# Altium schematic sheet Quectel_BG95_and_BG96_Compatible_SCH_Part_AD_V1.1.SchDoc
size 840 x 594 mm
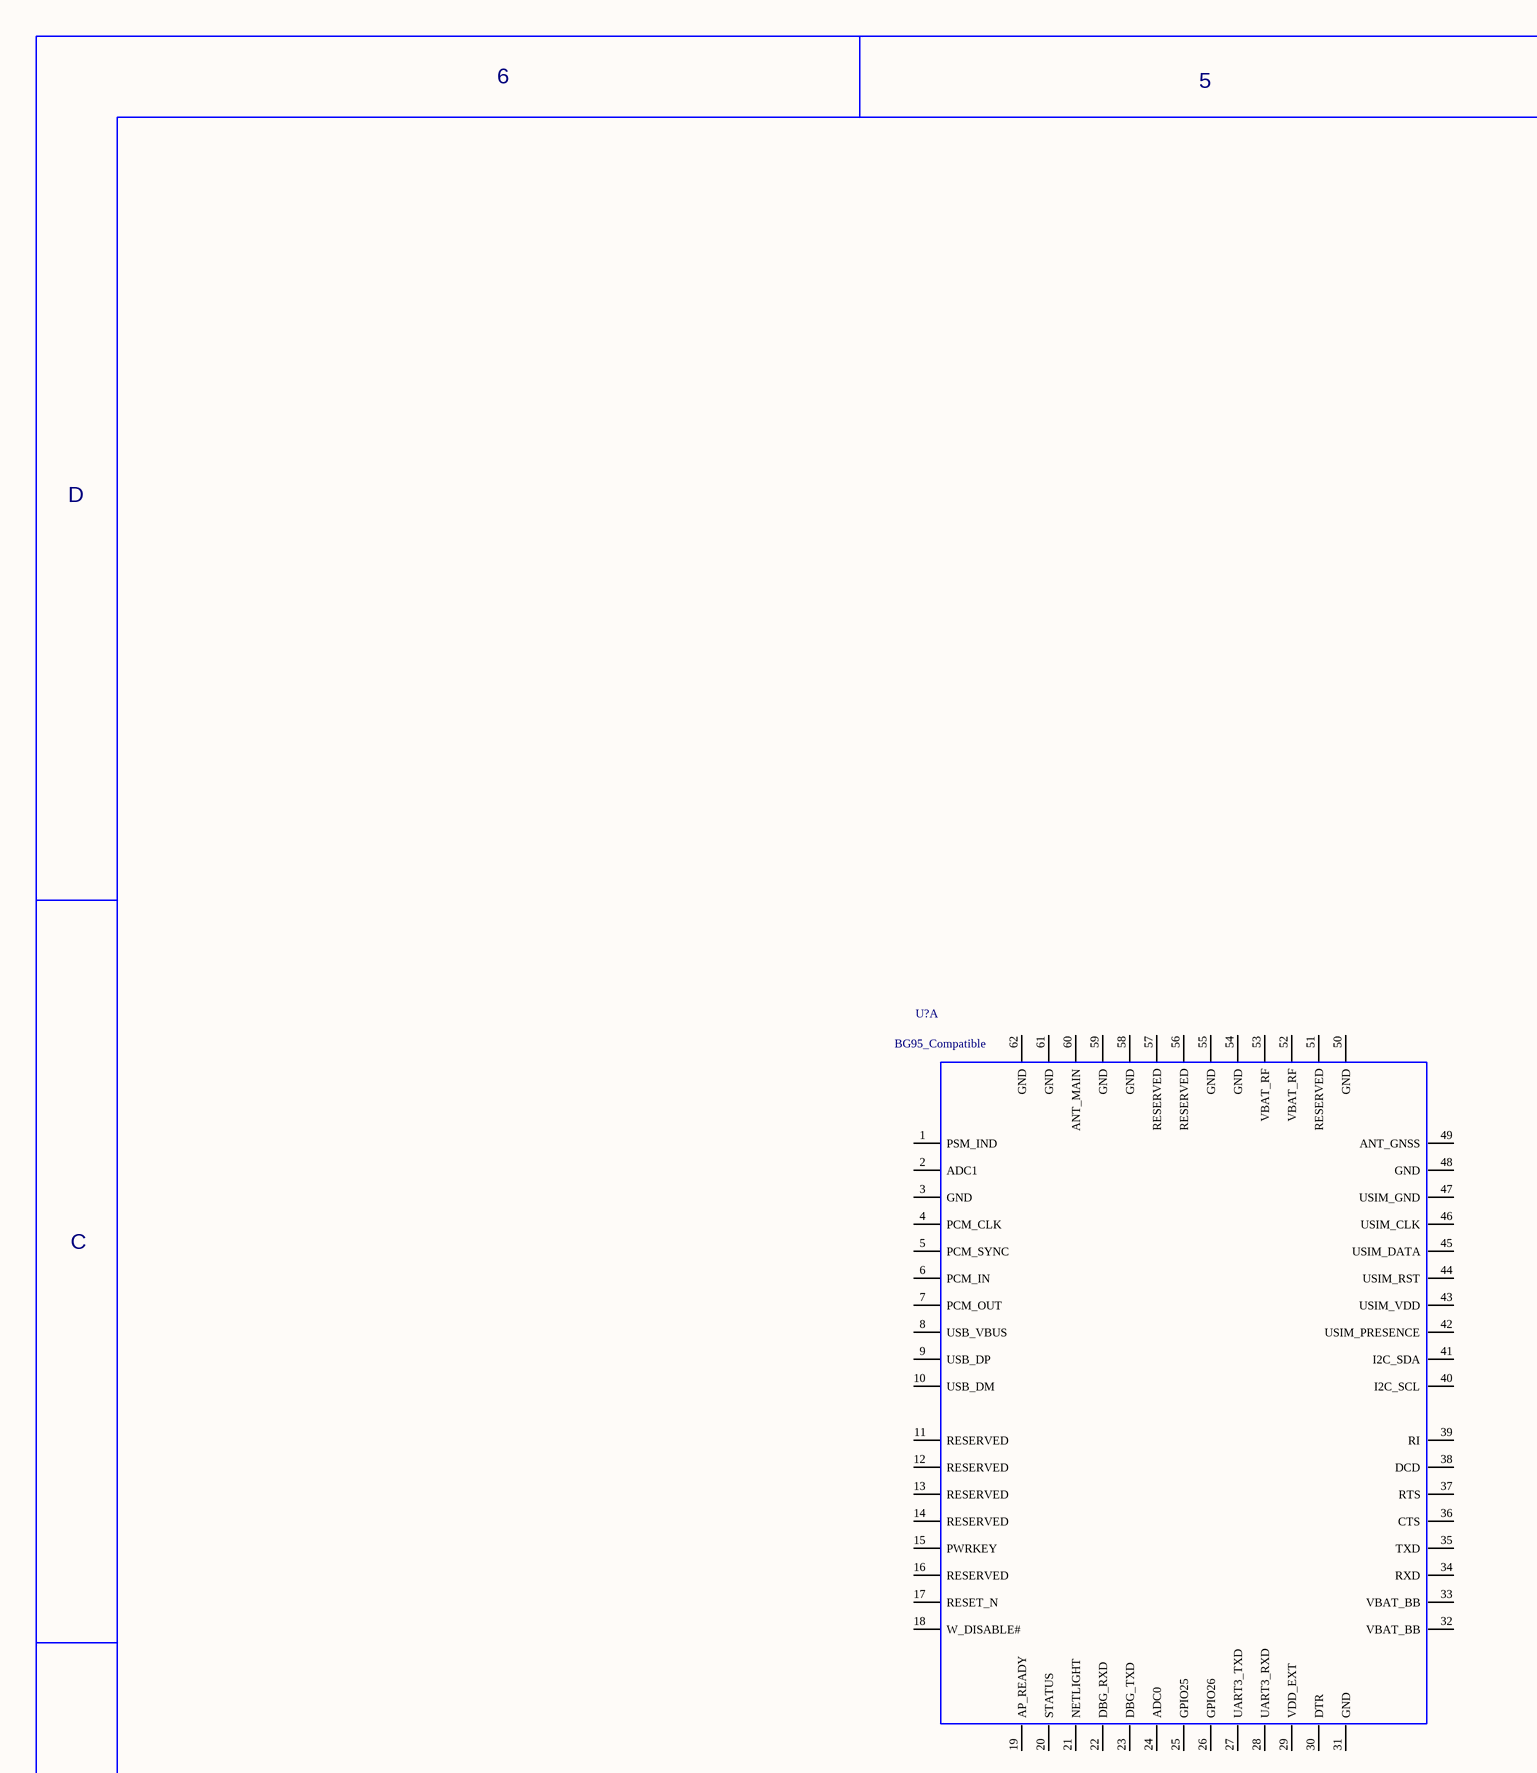
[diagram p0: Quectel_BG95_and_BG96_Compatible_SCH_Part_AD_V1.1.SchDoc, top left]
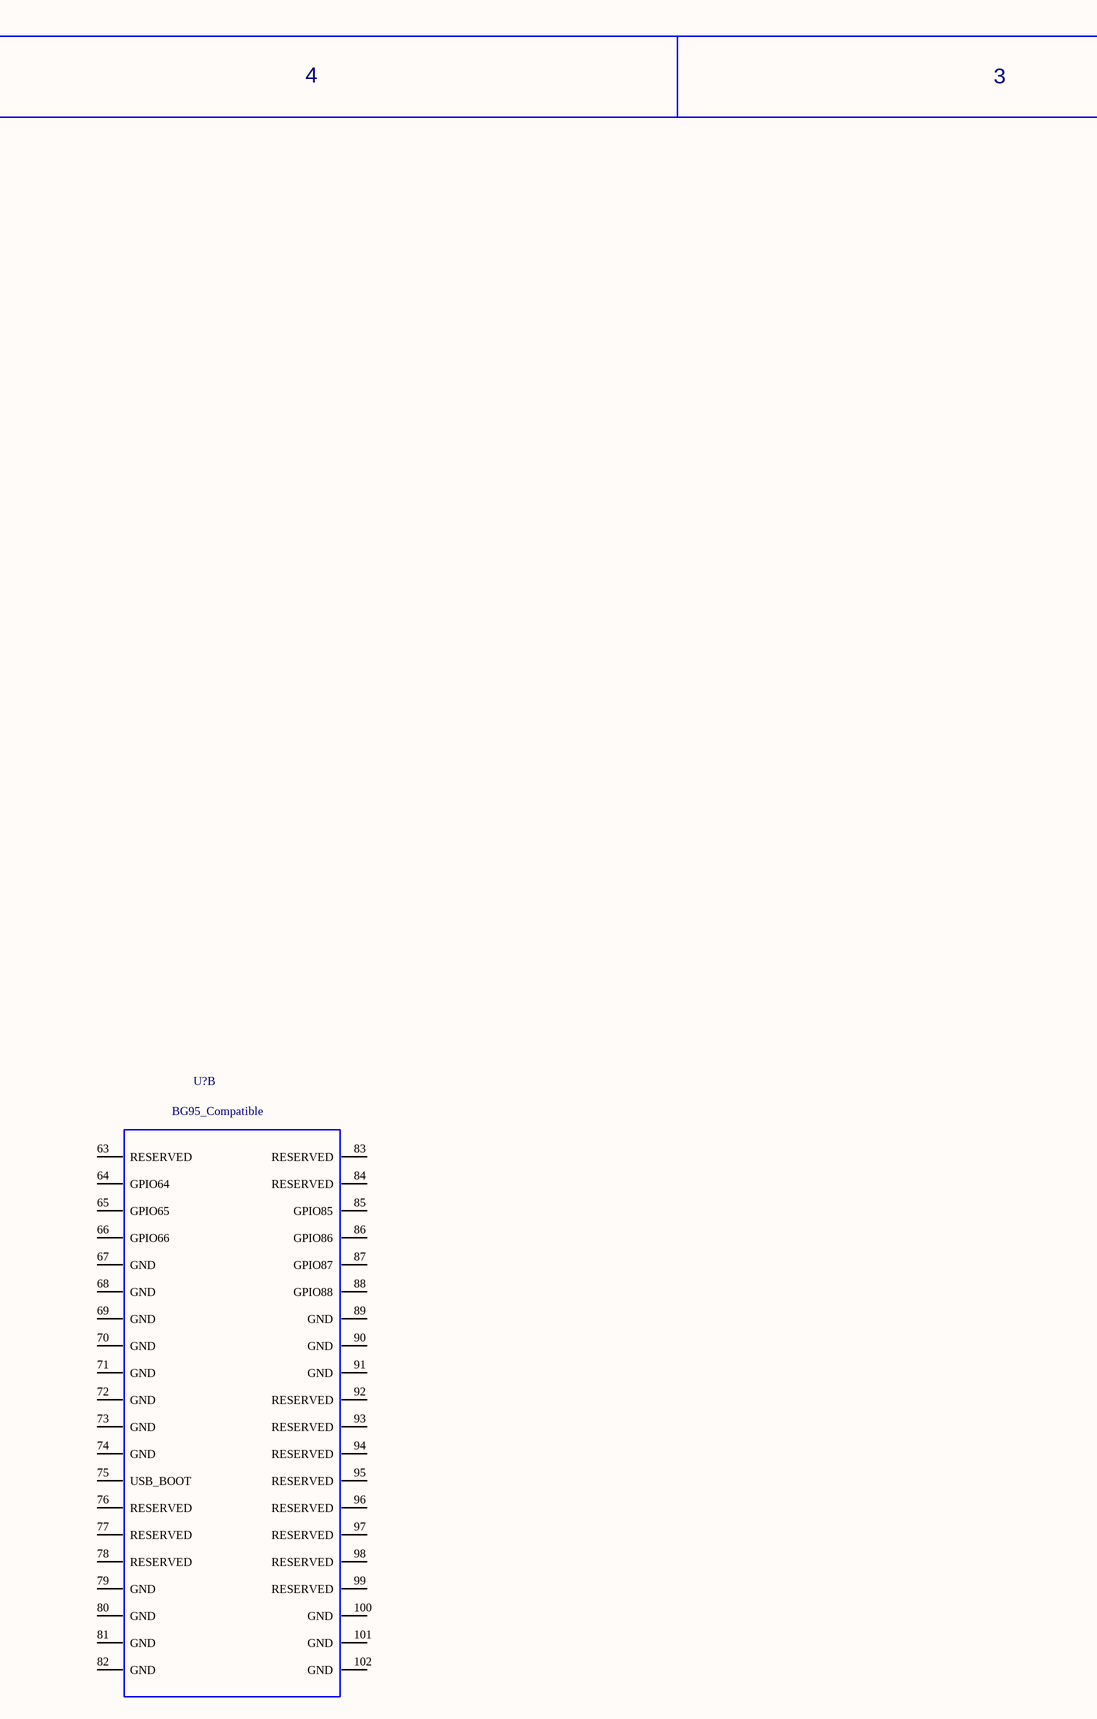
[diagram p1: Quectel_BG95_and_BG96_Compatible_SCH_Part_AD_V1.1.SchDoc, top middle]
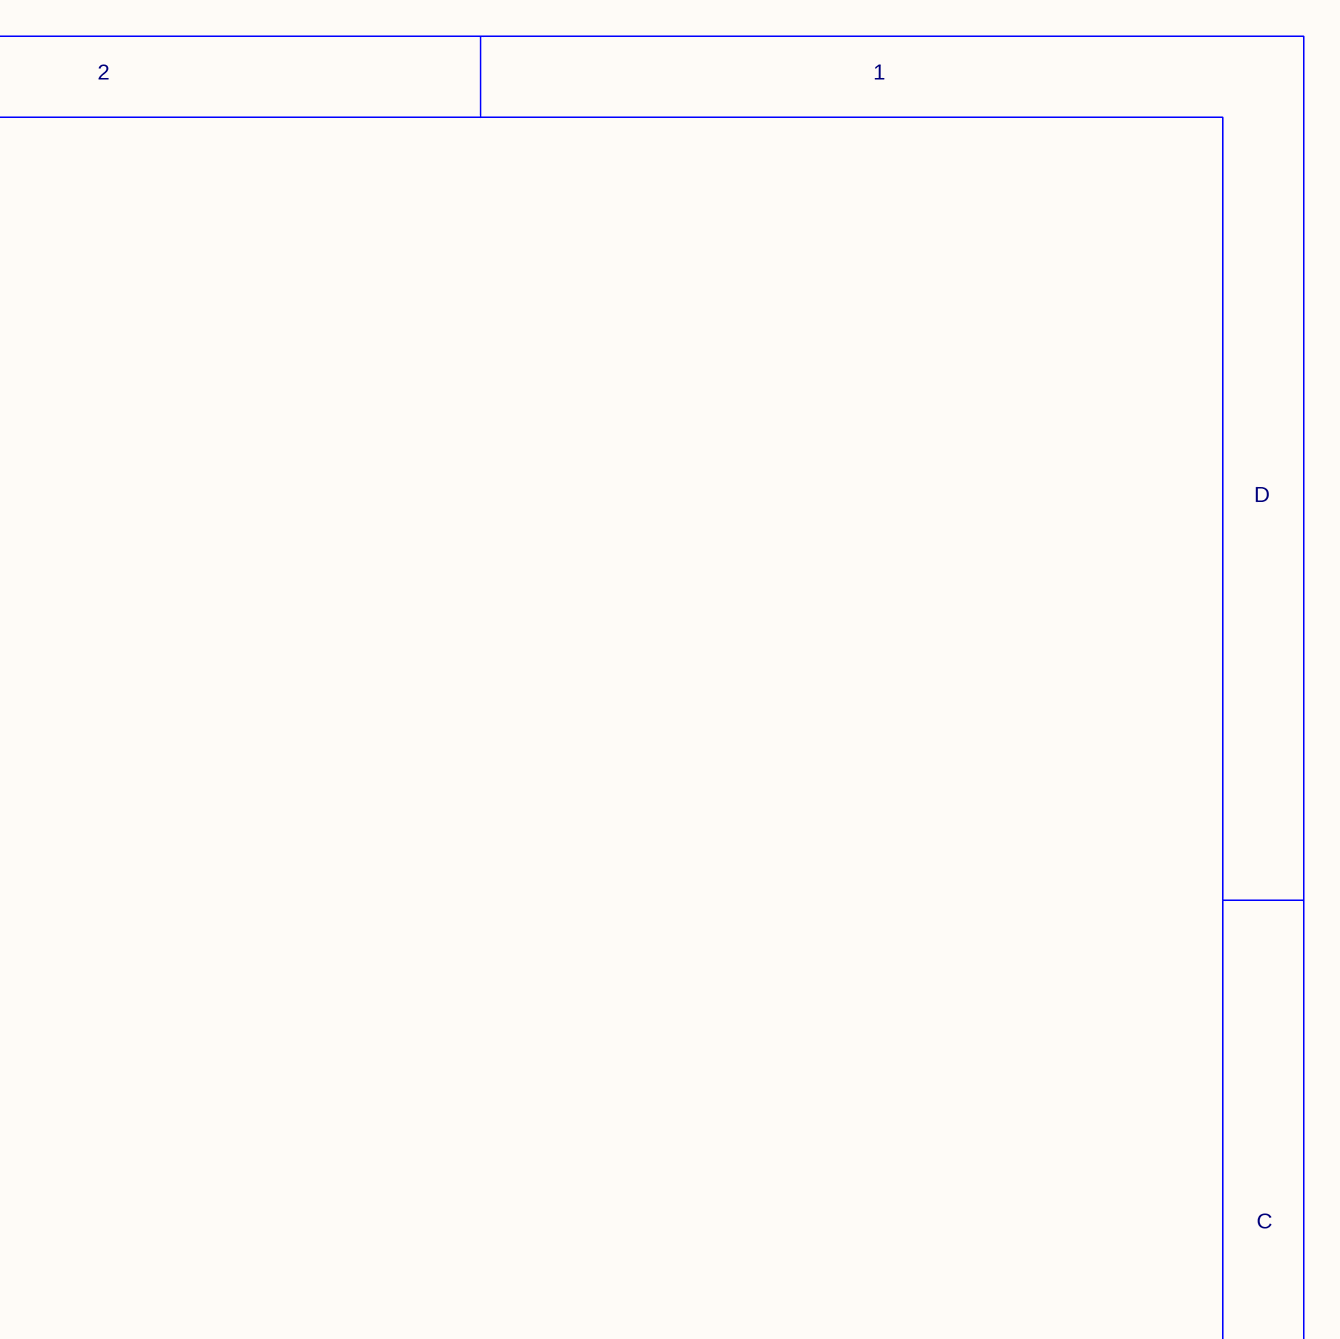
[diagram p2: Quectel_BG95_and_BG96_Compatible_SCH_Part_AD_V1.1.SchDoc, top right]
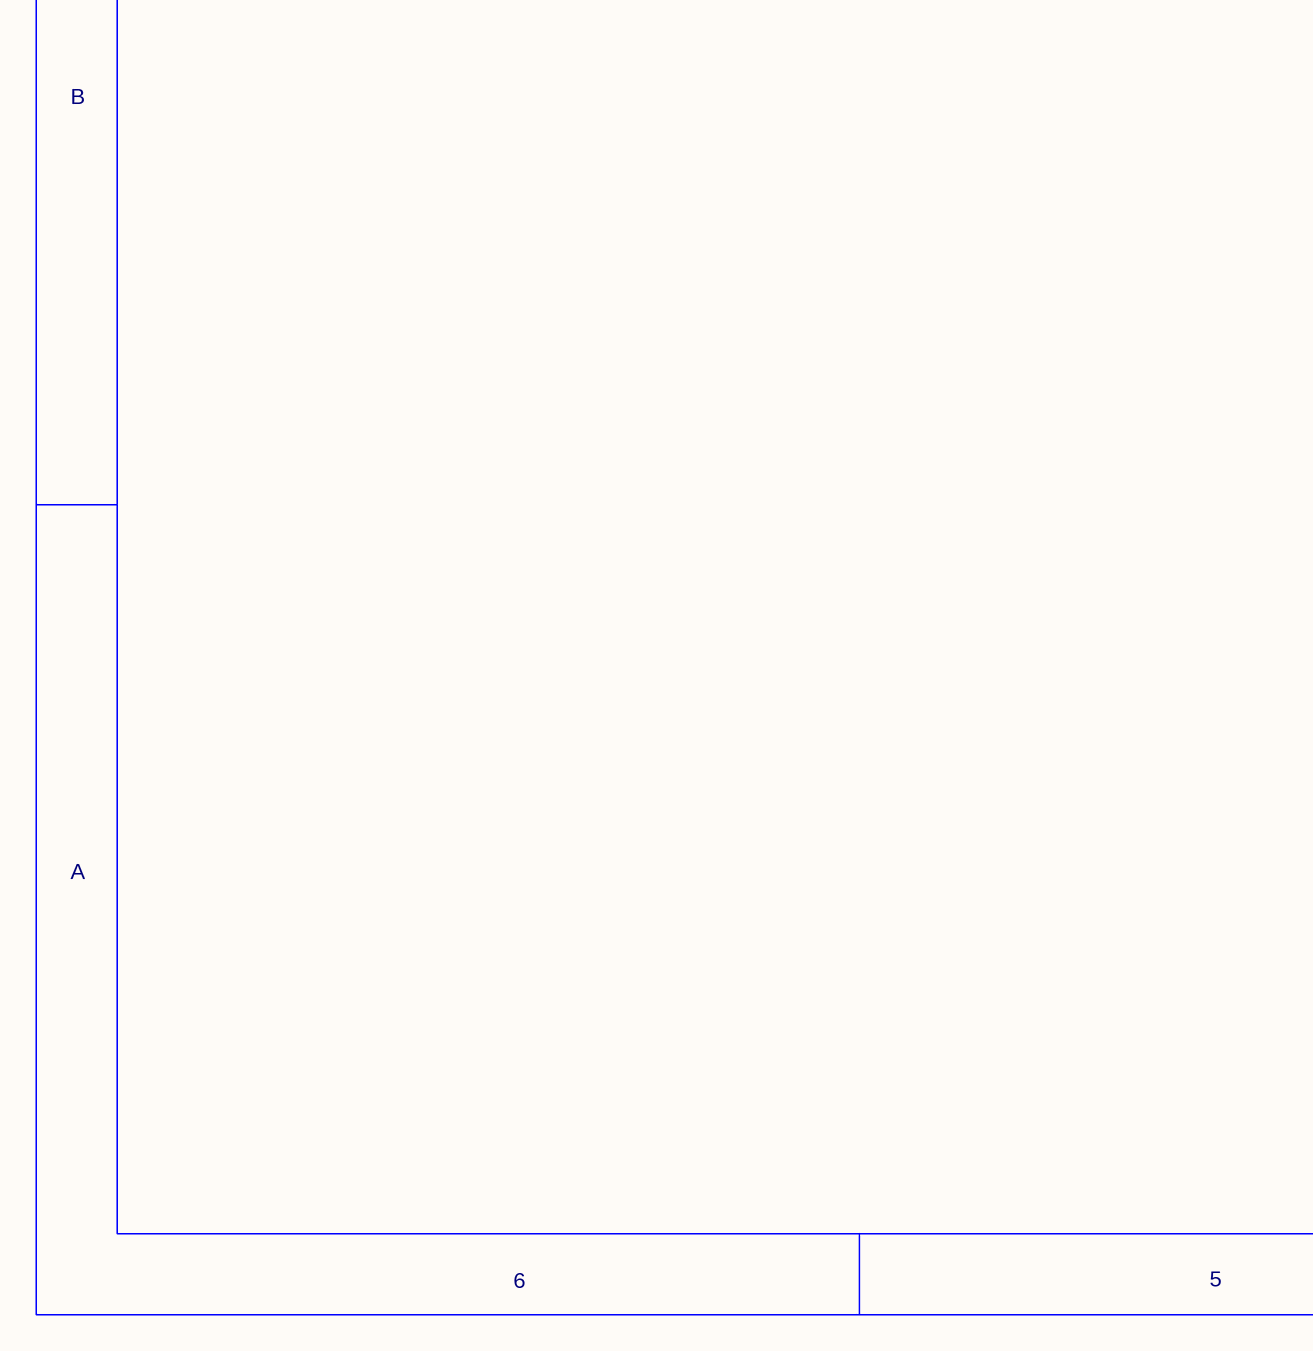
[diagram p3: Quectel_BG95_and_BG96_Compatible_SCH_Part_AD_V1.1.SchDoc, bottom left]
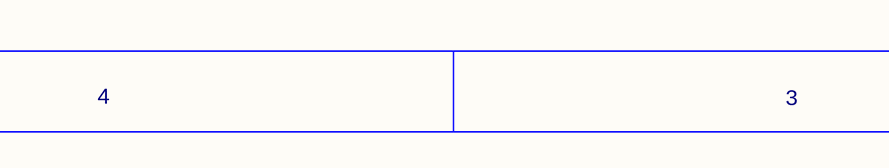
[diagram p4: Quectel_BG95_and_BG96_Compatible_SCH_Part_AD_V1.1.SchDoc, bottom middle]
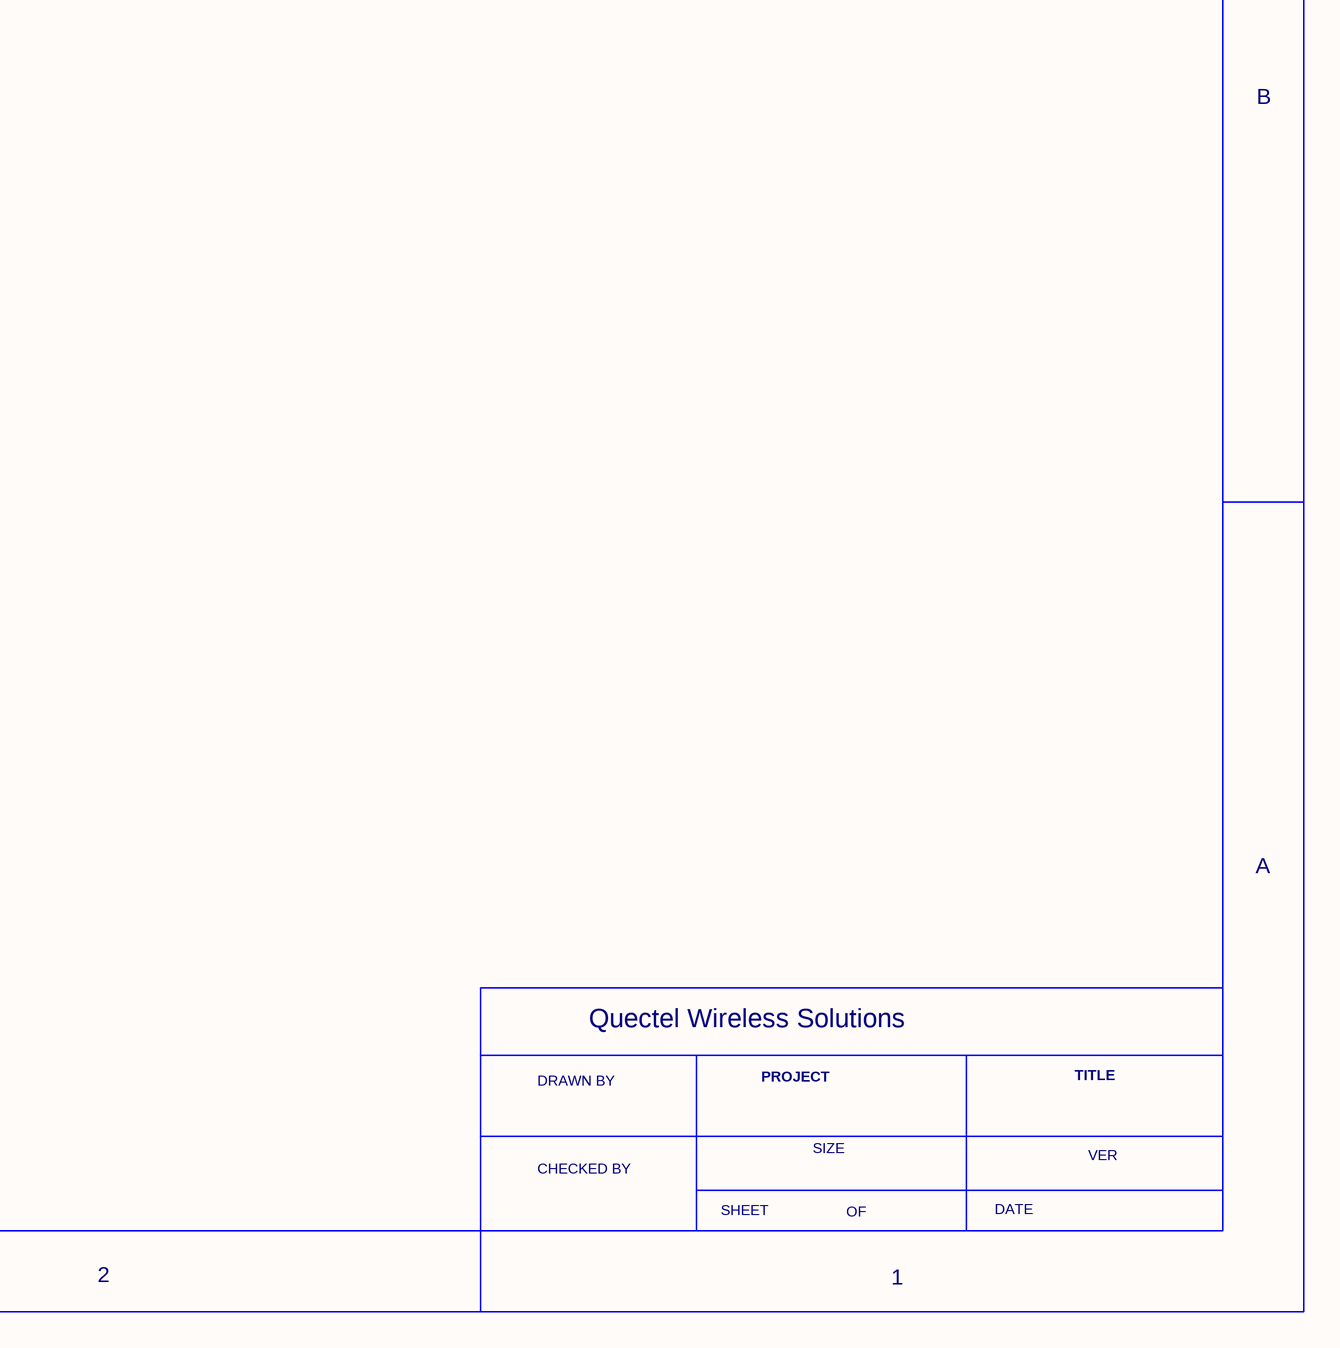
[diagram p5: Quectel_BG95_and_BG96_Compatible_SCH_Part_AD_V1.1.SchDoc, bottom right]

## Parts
(Parts that share a designator on the sheet are numbered #1, #2 ... from top to bottom, then left to right.)
U?#1  BG95_Compatible  [BG95_Compatible]  (part A of 2)
U?#2  BG95_Compatible  [BG95_Compatible]  (part B of 2)

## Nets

Not connected (* = marked no-connect by the designer): U?#1 1(PSM_IND) 2(ADC1) 3(GND) 4(PCM_CLK) 5(PCM_SYNC) 6(PCM_IN) 7(PCM_OUT) 8(USB_VBUS) 9(USB_DP) 10(USB_DM) 11(RESERVED) 12(RESERVED) 13(RESERVED) 14(RESERVED) 15(PWRKEY) 16(RESERVED) 17(RESET_N) 18(W_DISABLE#) 19(AP_READY) 20(STATUS) 21(NETLIGHT) 22(DBG_RXD) 23(DBG_TXD) 24(ADC0) 25(GPIO25) 26(GPIO26) 27(UART3_TXD) 28(UART3_RXD) 29(VDD_EXT) 30(DTR) 31(GND) 32(VBAT_BB) 33(VBAT_BB) 34(RXD) 35(TXD) 36(CTS) 37(RTS) 38(DCD) 39(RI) 40(I2C_SCL) 41(I2C_SDA) 42(USIM_PRESENCE) 43(USIM_VDD) 44(USIM_RST) 45(USIM_DATA) 46(USIM_CLK) 47(USIM_GND) 48(GND) 49(ANT_GNSS) 50(GND) 51(RESERVED) 52(VBAT_RF) 53(VBAT_RF) 54(GND) 55(GND) 56(RESERVED) 57(RESERVED) 58(GND) 59(GND) 60(ANT_MAIN) 61(GND) 62(GND); U?#2 63(RESERVED) 64(GPIO64) 65(GPIO65) 66(GPIO66) 67(GND) 68(GND) 69(GND) 70(GND) 71(GND) 72(GND) 73(GND) 74(GND) 75(USB_BOOT) 76(RESERVED) 77(RESERVED) 78(RESERVED) 79(GND) 80(GND) 81(GND) 82(GND) 83(RESERVED) 84(RESERVED) 85(GPIO85) 86(GPIO86) 87(GPIO87) 88(GPIO88) 89(GND) 90(GND) 91(GND) 92(RESERVED) 93(RESERVED) 94(RESERVED) 95(RESERVED) 96(RESERVED) 97(RESERVED) 98(RESERVED) 99(RESERVED) 100(GND) 101(GND) 102(GND)

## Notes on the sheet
- 6
- 5
- 4
- 3
- 2
- 1
- D
- C
- B
- A
- Quectel Wireless Solutions
- DRAWN BY
- PROJECT
- TITLE
- CHECKED BY
- SIZE
- VER
- SHEET
- OF
- DATE

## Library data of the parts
U?#1 = BG95: Manufacturer: QUECTEL; Part Description: IC MODULE BG95_Compatible 102-LGA 19.9x23.6mm H2.2mm RO; Geometry.Height: 2.2mm; Value: BG95BG95_Compatible
U?#2 = BG95: Manufacturer: QUECTEL; Part Description: IC MODULE BG95_Compatible 102-LGA 19.9x23.6mm H2.2mm RO; Geometry.Height: 2.2mm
